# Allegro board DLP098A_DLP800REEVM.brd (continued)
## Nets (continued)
N16883884: R35.2 U11.3(D-)
N16883892: TP38.1 U11.4(THERM)
N16884055: R22.2 U9.13(1B1)
N16884056: R23.2 U9.12(1B2)
N16884057: R24.2 U9.11(2B1)
N16884058: R25.2 U9.10(2B2)
N16884072: R30.1 U10.3(A)
N16949503: C79.2 U13.3(CBOOT)
N16949505: C79.1 L7.1 U13.1(SW#1) U13.2(SW#2)
N16949620: C89.1 R44.2 R47.2 U13.9(FB)
N16949632: R45.2 U13.7(RT)
N16949636: C90.2 U13.4(VCC)
N16949644: R46.2 U13.6(SYNC)
N16949726: C91.2 U13.11(SS/TRK)
N16949871: R49.1 R51.1 U16.1(G)
N16949907: R50.1 U15.1(G) U16.3(D)
N16950963: U6.1(G) U14.4(Y)
N16971448: R55.1 R56.2 U17.4(FB)

Pads without a net: J500 B16 B17 B20 B21 B25 B28 B29 C30 C31 C34 D01 D04 D05 D29 D30 D31 D33 D34 D35 E18 E19 E33 E34 E36 E37 F01 F19 F20 F37 F38 H02 J18 J19 J21 J22 J36 J37 K16 K17 K19 K20 K22 K23 K37 K38; L5 3 4; L6 3 4; NOREF#4 1; NOREF#6 1; NOREF#8 1; NOREF#19 1; NOREF#20 1; NOREF#23 1; NOREF#28 1; NOREF#29 1; NOREF#30 1; NOREF#31 1; U4 1; U5 3; U7 51 52; U8 G1 H1 J1 J3 J4 K3 P3 R1 R3 R4 T1 U1 V3; U14 1

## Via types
v1: diameter 0.61, hole 0.305, TOP to BOTTOM, 1186 vias
v2: diameter 0.4, hole 0.2, TOP to BOTTOM, 20 vias

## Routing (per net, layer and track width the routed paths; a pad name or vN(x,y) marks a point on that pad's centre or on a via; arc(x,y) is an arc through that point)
GND: length 525.4
  TOP w0.191: 95.3,23.42 95.12,23.6 U7.1 ; U7.60 80.7,22.98 v1(80.42,22.71) ; U7.20 94.11,33.83 v1(93.9,34.03)
  TOP w0.254: U7.41 80.7,33.83 v1(80.91,34.05) ; L5.1 103.35,28.8 103.4,28.84 ; U7.14 v1(92.75,30.1) ; U7.55 81.76,26.1 82.16,25.7 v1(82.58,25.7) 82.58,26.49 81.96,27.1 U7.53 ; U11.5 v1(104.29,8.4) ; U7.46 v1(82.53,30.6) ; U7.7 v1(92.72,26.6) ; 104.33,28.81 103.45,27.93
  TOP w0.381: C37.1 15.67,51.38 v1(17.07,51.38) ; C37.1 14.66,50.94 ; C37.1 15.78,50.94 ; C37.1 15.22,51.62 ; v1(120.12,29.06) 119.23,29.95 R52.2 ; 10.72,7.95 C72.1 ; C72.1 11.28,7.26 ; C72.1 v1(12.22,7.95) ; 50.01,7.26 C33.1 ; C33.1 v1(50.95,7.95) ; C33.1 49.46,7.95 ; 57.08,7.95 C67.1 ; C67.1 v1(58.57,7.95) ; C67.1 57.63,7.26 ; 21.44,7.26 C41.1 ; C41.1 20.88,7.95 ; C41.1 v1(22.38,7.95) ; C53.1 v1(26.19,7.95) ; C53.1 24.69,7.95 ; C53.1 25.25,7.26 ; 17.07,7.95 C31.1 ; C31.1 v1(18.57,7.95) ; C31.1 17.63,7.26 ; C69.1 v1(62.38,7.95) ; C69.1 61.44,7.26 ; C69.1 60.89,7.95 ; C51.1 18.96,51.86 v1(18.15,51.86) ; C51.1 19.84,51.67 ; C51.1 19.28,50.98 ; C51.1 20.4,50.98 ; 59.54,7.26 C68.1 ; C68.1 v1(60.48,7.95) ; C68.1 58.98,7.95 ; 8.82,7.95 C55.1 ; C55.1 9.37,7.26 ; C55.1 v1(10.31,7.95) ; C36.1 21.49,51.67 ; C36.1 20.93,50.98 ; C36.1 21.62,50.98 v1(22.58,50.02) ; U4.3 109.87,42 v1(110,41.87) ; 43.36,50.81 C47.1 ; C47.1 44.48,50.81 ; C47.1 v1(43.92,51.88) ; U13.5 115.73,8.41 v1(115.29,7.98) ; C7.1 101.03,66.96 v1(100.83,66.76) ; 45.65,7.95 C63.1 ; C63.1 46.2,7.26 ; C63.1 v1(47.14,7.95) ; C84.2 v1(129.52,17.5) ; C46.1 13.62,51.8 ; C46.1 C52.1 ; C46.1 14.18,51.11 ; 18.98,7.95 C32.1 ; C32.1 v1(20.47,7.95) ; C32.1 19.53,7.26 ; C35.1 42.83,50.81 ; C35.1 41.71,50.81 ; C35.1 v1(42.27,51.88) ; v1(32.11,50.73) C57.1 30.31,50.73 30.26,50.77 ; R13.2 102.13,40.49 v1(101.7,40.06) ; C52.1 11.59,51.97 11.61,51.99 ; C52.1 10.74,51.11 v1(10.53,50.9) ; v1(30,7.95) C71.1 v1(28.09,7.95) C54.1 ; 36.68,7.26 C45.1 ; C45.1 36.12,7.95 ; C45.1 v1(37.62,7.95) ; 39.98,50.86 C50.1 ; C50.1 v1(40.54,51.93) ; C50.1 41.1,50.86 ; 12.63,7.95 C43.1 ; C43.1 v1(14.12,7.95) ; C43.1 13.18,7.26 ; 35.69,50.76 35.65,50.8 C65.1 v1(34.77,51.87) ; C24.1 v1(107.16,29.82) ; 41.2,7.95 C56.1 ; C56.1 41.76,7.26 ; C56.1 v1(42.7,7.95) ; C66.1 v1(56.67,7.95) ; C66.1 55.17,7.95 ; C66.1 55.73,7.26 ; C87.2 v1(128.75,16.99) ; 36.55,50.86 C58.1 ; C58.1 v1(37.11,51.93) ; C58.1 37.67,50.86 ; 53.27,7.95 C34.1 ; C34.1 v1(54.76,7.95) ; C34.1 53.82,7.26 ; C61.1 v1(49.05,7.95) ; C61.1 48.11,7.26 ; C61.1 47.55,7.95 ; C48.1 v1(38.64,51.93) ; C48.1 38.08,50.86 ; C48.1 39.2,50.86 ; v1(105,27.44) 105,27.55 104.62,27.93 L5.1 ; 95.3,23.42 v1(95.55,23.17) ; 26.6,7.95 C54.1 ; C54.1 27.15,7.26 ; 28.68,50.73 C39.1 ; C39.1 28.78,51.19 v1(28.52,51.19) ; C39.1 29.8,50.73 ; 23.34,7.26 C59.1 ; C59.1 22.79,7.95 ; C59.1 v1(24.28,7.95) ; v1(99.52,41.05) 99.47,40.99 D1.1 97.78,42.09 v1(97.24,42.63) ; R18.1 78.49,38.62 v1(78.18,38.93) ; v1(130.86,5.97) 130.86,5.97 C86.2 127.38,5.97 v1(126.85,5.44) ; 33.5,7.26 C70.1 ; C70.1 v1(34.44,7.95) ; C70.1 32.95,7.95 ; C29.1 v1(100.18,21.94) ; C22.1 v1(108.77,36.2) ; 44.3,7.26 C62.1 ; C62.1 v1(45.24,7.95) ; C62.1 43.74,7.95 ; v1(116.69,24.36) 117.59,25.26 U16.2 ; C77.1 v1(100.33,13.13) ; C21.1 v1(107.8,37.41) ; C1.1 v1(108.55,68.15) ; C30.1 v1(97.64,24.59) ; 39.22,7.26 C44.1 ; C44.1 v1(40.16,7.95) ; C44.1 38.66,7.95 ; v1(46.51,51.93) C42.1 45.68,50.86 45.65,50.83 ; C40.1 v1(52.86,7.95) ; C40.1 51.92,7.26 ; C40.1 51.36,7.95 ; D5.A v1(121.77,5.44) ; 15.72,7.26 C60.1 ; C60.1 15.17,7.95 ; C60.1 v1(16.66,7.95) ; v1(106.39,39.98) 107.16,40.74 R14.2 ; C8.1 v1(103.69,69.1) ; C64.1 v1(32.54,7.95) ; C64.1 31.6,7.26 ; C64.1 31.04,7.95 ; C49.1 v1(54.89,48.09) ; C23.1 v1(110.67,36.2) ; C2.1 v1(104.99,66.79) ; C38.1 v1(50.24,48.06) ; R19.2 v1(80.8,16.04)
  TOP w0.508: U8.Y9 v1(27.15,16.99) ; U8.B25 v1(48.74,42.39) ; U8.J24 v1(47.47,33.5) ; U8.X20 v1(42.39,18.26) ; U8.V24 v1(47.47,20.8) ; U8.F24 v1(47.47,37.31) ; U8.V4 v1(20.8,20.8) ; U8.H26 v1(50.01,34.77) ; v1(103.96,7.08) J3.4 v1(103.96,3.92) ; U8.L3 v1(19.53,30.96) ; U8.Y22 v1(44.93,16.99) ; U8.T2 v1(18.26,23.34) ; U8.V23 v1(46.2,20.8) ; U8.B7 v1(24.61,42.39) ; U8.D20 v1(42.39,39.85) ; U8.D9 v1(27.15,39.85) ; U8.X18 v1(39.85,18.26) ; U8.C24 v1(47.47,41.12) ; U8.E1 v1(16.99,38.58) ; U8.C9 v1(27.15,41.12) ; U8.L2 v1(18.26,30.96) ; U8.R24 v1(47.47,24.61) ; U8.E9 v1(27.15,38.58) ; U8.E2 v1(18.26,38.58) ; U8.L4 v1(20.8,30.96) ; U8.Z25 v1(48.74,15.72) ; U8.E16 v1(37.31,38.58) ; U8.M23 v1(46.2,28.42) ; U8.D2 v1(18.26,39.85) ; U8.Z20 v1(42.39,15.72) ; U8.X14 v1(34.77,18.26) ; U8.Z11 v1(29.69,15.72) ; U8.W1 v1(16.99,19.53) ; U8.H2 v1(18.26,34.77) ; U8.F4 v1(20.8,37.31) ; U8.W2 v1(18.26,19.53) ; U8.P2 v1(18.26,25.88) ; U8.X9 v1(27.15,18.26) ; U8.E26 v1(50.01,38.58) ; U8.B11 v1(29.69,42.39) ; U8.D18 v1(39.85,39.85) ; U8.E18 v1(39.85,38.58) ; U8.Y20 v1(42.39,16.99) ; U8.B4 v1(20.8,42.39) ; U8.D11 v1(29.69,39.85) ; U8.Y24 v1(47.47,16.99) ; U8.Z7 v1(24.61,15.72) ; U8.Y2 v1(18.26,16.99) ; U8.R23 v1(46.2,24.61) ; U8.X2 v1(18.26,18.26) ; U8.M1 v1(16.99,28.42) ; U8.H4 v1(20.8,34.77) ; U8.N2 v1(18.26,27.15) ; U8.D14 v1(34.77,39.85) ; U8.T26 v1(50.01,23.34) ; U8.D21 v1(43.66,39.85) ; U8.W25 v1(48.74,19.53) ; U8.Z22 v1(44.93,15.72) ; U8.B17 v1(38.58,42.39) ; U8.B20 v1(42.39,42.39) ; U8.W26 v1(50.01,19.53) ; U8.B22 v1(44.93,42.39) ; U8.E25 v1(48.74,38.58) ; U8.C22 v1(44.93,41.12) ; U8.W7 v1(24.61,19.53) ; U8.N3 v1(19.53,27.15) ; U8.C20 v1(42.39,41.12) ; U8.M2 v1(18.26,28.42) ; U8.T4 v1(20.8,23.34) ; U8.Z17 v1(38.58,15.72) ; U8.X5 v1(22.07,18.26) ; U8.X21 v1(43.66,18.26) ; U8.E17 v1(38.58,38.58) ; U8.B14 v1(34.77,42.39) ; U8.Z14 v1(34.77,15.72) ; U8.N4 v1(20.8,27.15) ; U8.J23 v1(46.2,33.5) ; U8.M24 v1(47.47,28.42) ; U8.C2 v1(18.26,41.12) ; U8.E7 v1(24.61,38.58) ; U8.F23 v1(46.2,37.31) ; U8.Z4 v1(20.8,15.72) ; U8.D1 v1(16.99,39.85) ; U8.W9 v1(27.15,19.53) ; U8.X1 v1(16.99,18.26) ; U8.D5 v1(22.07,39.85) ; U8.T25 v1(48.74,23.34) ; U8.X11 v1(29.69,18.26) ; U8.K2 v1(18.26,32.23) ; U8.H25 v1(48.74,34.77)
  02_GND1 w0.381: TP12.1 117.93,50.95 ; TP12.1 116.49,49.5 ; TP12.1 117.93,48.06 ; TP12.1 119.38,49.5
  04_GND2 w0.381: 116.49,49.5 TP12.1 ; TP12.1 117.93,48.06 ; TP12.1 117.93,50.95 ; TP12.1 119.38,49.5
  09_GND3 w0.381: TP12.1 119.38,49.5 ; TP12.1 117.93,50.95 ; TP12.1 116.49,49.5 ; TP12.1 117.93,48.06
  11_GND4 w0.381: TP12.1 117.93,50.95 ; TP12.1 119.38,49.5 ; TP12.1 116.49,49.5 ; TP12.1 117.93,48.06
  BOTTOM w0.254: U9.15 23.8,53.22 24.3,52.72 ; v1(114.4,37.83) 114.61,37.62 U1.5 ; 24.3,52.72 U9.17 ; 24.3,52.72 U9.14 22.6,52.72 22.29,53.03 22.29,53.44 v1(22.3,53.45) ; v1(25.8,48.92) U9.8 25.8,51.22 U9.17 ; U9.17 24.3,51.22 U9.9 v1(24.3,48.94) ; v1(90.06,36.52) 89.54,36 C28.1 ; C73.1 v1(19.84,55.78)
  BOTTOM w0.305: U10.2 v1(14.4,52.23)
  BOTTOM w0.381: J500.B33 v1(94.91,84.6) ; J500.B13 v1(68.24,84.6) ; J500.C24 v1(83.48,83.33) ; J500.J14 v1(69.51,74.44) ; C80.2 124.51,15.85 ; C80.2 123.04,14.88 ; C80.2 123.04,16.81 ; C80.2 121.57,15.85 ; J500.C21 v1(79.67,83.33) ; v1(96.81,66.64) 97.06,66.9 C3.1 ; J500.G01 v1(53,76.98) ; J500.K36 v1(98.72,73.17) ; J500.B31 v1(92.37,84.6) ; J500.G35 v1(97.45,76.98) ; C74.1 v1(31.14,55.41) ; R26.1 32.15,52.99 v1(32.83,52.32) 32.23,51.72 R27.1 ; J500.C36 v1(98.72,83.33) ; J500.B39 v1(102.53,84.6) ; J500.G20 v1(77.13,76.98) ; J500.C33 v1(94.91,83.33) ; J500.D28 v1(88.56,82.06) ; R44.1 C89.2 ; J500.B03 v1(55.54,84.6) ; J500.E04 v1(56.81,80.79) ; J500.A09 v1(63.16,85.87) ; J500.E35 v1(97.45,80.79) ; v1(92.75,30.1) 93.01,29.84 C17.1 ; J500.C12 v1(66.97,83.33) ; J500.E40 v1(103.8,80.79) ; C82.2 119.23,16.81 ; C82.2 117.76,15.85 ; C82.2 120.7,15.85 ; C82.2 119.23,14.88 ; J500.A04 v1(56.81,85.87) ; J500.A16 v1(72.05,85.87) ; J500.E32 v1(93.64,80.79) ; J500.G11 v1(65.7,76.98) ; v1(100.18,15.72) C93.1 v1(102.59,17.5) ; v1(127.14,42.58) 127.52,42.58 128.1,43.16 U14.3 ; v1(80.91,34.05) 80.98,34.11 C27.1 ; J500.A17 v1(73.32,85.87) ; J500.G05 v1(58.08,76.98) ; J500.H15 v1(70.78,75.71) ; J500.H21 v1(79.67,75.71) ; J500.H06 v1(59.35,75.71) ; J500.A24 v1(83.48,85.87) ; v1(122.07,37.37) 121.82,37.12 R9.1 ; C9.1 v1(117.4,40.95) ; C19.1 82.25,30.33 v1(82.53,30.6) ; C76.1 v1(11.99,55.37) ; J500.F12 v1(66.97,78.25) ; J500.B18 v1(74.59,84.6) ; v1(103.61,26.03) 104.39,25.25 R56.1 ; J500.G32 v1(93.64,76.98) ; C10.1 108.94,32.36 v1(109.86,33.27) ; J500.G04 v1(56.81,76.98) ; J500.F30 v1(91.1,78.25) ; J500.D10 v1(64.43,82.06) ; J500.B19 v1(75.86,84.6) ; J500.K30 v1(91.1,73.17) ; J500.E01 v1(53,80.79) ; J500.C40 v1(103.8,83.33) ; J500.C28 v1(88.56,83.33) ; U2.3 113.85,28.99 v1(113.64,29.19) ; J500.D06 v1(59.35,82.06) ; J500.A33 v1(94.91,85.87) ; J500.E23 v1(82.21,80.79) ; C94.1 99.42,24.77 v1(98.1,23.44) ; R15.2 v1(125.66,37.59) ; J500.G14 v1(69.51,76.98) ; J500.K06 v1(59.35,73.17) ; J500.G23 v1(82.21,76.98) ; J500.D22 v1(80.94,82.06) ; J500.C20 v1(77.13,83.33) ; J500.A27 v1(87.29,85.87) ; J500.A35 v1(97.45,85.87) ; J500.J32 v1(93.64,74.44) ; J500.B14 v1(69.51,84.6) ; J500.F15 v1(70.78,78.25) ; C4.1 v1(99.73,69.36) ; J500.G38 v1(101.26,76.98) ; J500.A05 v1(58.08,85.87) ; v1(93.45,22.33) 93.09,21.98 C26.1 ; J500.A08 v1(61.89,85.87) ; J500.B35 v1(97.45,84.6) ; J500.K02 v1(54.27,73.17) ; J500.C01 v1(53,83.33) ; J500.C29 v1(89.83,83.33) ; J500.F27 v1(87.29,78.25) ; R17.1 81.33,32.06 v1(82.15,32.88) ; C5.1 v1(95.77,69.31) ; J500.F03 v1(55.54,78.25) ; J500.K15 v1(70.78,73.17) ; J500.G17 v1(73.32,76.98) ; J500.A12 v1(68.24,85.87) J500.A13 ; J500.J08 v1(61.89,74.44) ; J500.J01 v1(53,74.44) ; v1(116.49,38.12) U1.7 ; J500.A11 v1(65.7,85.87) ; J500.D02 v1(54.27,82.06) ; J500.D16 v1(72.05,82.06) ; J500.K39 v1(102.53,73.17) ; J500.E05 v1(58.08,80.79) ; J500.A28 v1(88.56,85.87) ; J500.G08 v1(61.89,76.98) ; J500.D37 v1(99.99,82.06) ; C12.1 109.45,25.02 v1(109.5,24.97) ; J500.D25 v1(84.75,82.06) ; J500.J04 v1(56.81,74.44) ; J500.J38 v1(101.26,74.44) ; J500.B09 v1(63.16,84.6) ; U17.3 v1(105.89,18.14) ; C16.1 98.25,39.78 v1(99.52,41.05) ; J500.H03 v1(55.54,75.71) ; C20.1 v1(76.68,34.09) ; J500.K09 v1(63.16,73.17) ; J500.E29 v1(89.83,80.79) ; J500.H27 v1(87.29,75.71) ; J500.K24 v1(83.48,73.17) ; J500.J26 v1(86.02,74.44) ; J500.H30 v1(91.1,75.71) ; J500.J35 v1(97.45,74.44) ; U6.2 123.36,42.91 v1(123.37,42.9) ; J500.K12 v1(66.97,73.17) ; J500.E26 v1(86.02,80.79) ; C6.1 v1(92.26,67.43) ; J500.J05 v1(58.08,74.44) ; J500.A19 v1(75.86,85.87) ; J500.A36 v1(98.72,85.87) ; J500.H09 v1(63.16,75.71) ; J500.A39 v1(102.53,85.87) ; C15.1 82.03,28.55 v1(82.91,28.55) ; J500.B26 v1(86.02,84.6) ; J500.C38 v1(101.26,83.33) ; C75.1 14.73,52.23 v1(14.4,52.23) ; J500.A29 v1(89.83,85.87) ; v1(79.35,22.84) 79.35,24.03 79.73,24.42 C18.1 ; C11.1 v1(121.9,40.24) ; v1(105.89,11.91) U17.6 102.77,13.87 v1(102.74,13.84) ; R21.1 v1(9.83,53.37) ; J500.F36 v1(98.72,78.25) ; J500.C07 v1(60.62,83.33) ; J500.B05 v1(58.08,84.6) ; J500.E17 v1(73.32,80.79) ; C13.1 v1(83.67,16.11) ; J500.C05 v1(58.08,83.33) ; J500.F02 v1(54.27,78.25) ; J500.E20 v1(77.13,80.79) ; J500.A37 v1(99.99,85.87) ; J500.J17 v1(73.32,74.44) ; J500.J11 v1(65.7,74.44) ; J500.E14 v1(69.51,80.79) ; J500.C32 v1(93.64,83.33) ; J500.C17 v1(73.32,83.33) ; J500.A03 v1(55.54,85.87) ; J500.H33 v1(94.91,75.71) ; J500.B15 v1(70.78,84.6) ; J500.D19 v1(75.86,82.06) ; J500.K33 v1(94.91,73.17) ; J500.J29 v1(89.83,74.44) ; J500.C25 v1(84.75,83.33) ; J500.K21 v1(79.67,73.17) ; J500.B23 v1(82.21,84.6) ; J500.C08 v1(61.89,83.33) ; J500.A23 v1(82.21,85.87) ; J500.C13 v1(68.24,83.33) ; v1(130.97,8.23) C85.2 127.25,8.23 v1(126.71,7.68) ; v1(32.11,50.73) 32.11,50.67 31.73,50.29 30.95,50.29 R28.1 R29.1 ; J500.J23 v1(82.21,74.44) ; J500.B10 v1(64.43,84.6) ; J500.B11 v1(65.7,84.6) ; J500.H24 v1(83.48,75.71) ; J500.F18 v1(74.59,78.25) ; J500.C16 v1(72.05,83.33) ; J500.A15 v1(70.78,85.87) ; J500.F09 v1(63.16,78.25) ; J500.B02 v1(54.27,84.6) ; J500.B30 v1(91.1,84.6) ; J500.B37 v1(99.99,84.6) ; J500.B06 v1(59.35,84.6) ; U5.2 v1(128.45,41.48) ; J500.B38 v1(101.26,84.6) ; J500.D03 v1(55.54,82.06) ; J500.B22 v1(80.94,84.6) ; J500.A25 v1(84.75,85.87) ; J500.E08 v1(61.89,80.79) ; J500.A21 v1(79.67,85.87) ; C25.1 v1(87.35,15.86) ; J500.F24 v1(83.48,78.25) ; J500.H36 v1(98.72,75.71) ; J500.G40 v1(103.8,76.98) ; J500.A31 v1(92.37,85.87) ; J500.A01 v1(53,85.87) ; J500.A40 v1(103.8,85.87) ; J500.B27 v1(87.29,84.6) ; J500.E38 v1(101.26,80.79) ; J500.H39 v1(102.53,75.71) ; J500.B34 v1(96.18,84.6) ; J500.C04 v1(56.81,83.33) ; J500.A32 v1(93.64,85.87) ; C14.1 v1(89.38,15.7) ; J500.A20 v1(77.13,85.87) ; J500.K27 v1(87.29,73.17) ; J500.H12 v1(66.97,75.71) ; R31.1 v1(10.39,48.59) ; J500.D13 v1(68.24,82.06) ; J500.G29 v1(89.83,76.98) ; J500.A07 v1(60.62,85.87) ; J500.H18 v1(74.59,75.71) ; J500.C03 v1(55.54,83.33) ; J500.F06 v1(59.35,78.25) ; J500.F39 v1(102.53,78.25) ; J500.C09 v1(63.16,83.33) ; J500.D39 v1(102.53,82.06) ; J500.B07 v1(60.62,84.6) ; J500.D07 v1(60.62,82.06) ; J500.F21 v1(79.67,78.25) ; J500.K03 v1(55.54,73.17) ; J500.E11 v1(65.7,80.79) ; J500.G26 v1(86.02,76.98) ; J500.K18 v1(74.59,73.17) ; J500.F33 v1(94.91,78.25) ; J500.J40 v1(103.8,74.44) ; J500.J20 v1(77.13,74.44)
  BOTTOM w1.016: v1(123.67,17.63) 125.2,17.63 125.83,16.99 125.83,12.04 123.04,9.25 C89.2
  vias: v1(0.99,49.25) v1(0.99,46.71) v1(0.99,44.17) v1(0.99,41.63) v1(0.99,39.09) v1(0.99,36.55) v1(0.99,34.01) v1(0.99,31.47) v1(0.99,28.93) v1(0.99,26.39) v1(0.99,23.85) v1(0.99,21.31) v1(0.99,18.77) v1(0.99,16.23) v1(0.99,13.69) v1(0.99,11.15) v1(0.99,8.61) v1(0.99,6.07) v1(0.99,3.53) v1(1.63,0.99) v1(2.55,51.15) v1(4.17,0.99) v1(4.34,52.94) v1(6.14,54.74) v1(6.71,0.99) v1(7.94,56.53) v1(9.25,0.99) v1(9.73,58.33) v1(11.53,60.13) v1(11.79,0.99) v1(13.32,61.92) v1(14.33,0.99) v1(15.12,63.72) v1(16.92,65.51) v1(16.87,0.99) v1(18.71,67.31) v1(19.41,0.99) v1(20.55,69.01) v1(21.95,0.99) v1(22.45,69.01) v1(24.36,69.01) v1(24.49,0.99) v1(26.26,69.01) v1(27.03,0.99) v1(28.17,69.01) v1(29.57,0.99) v1(30.07,69.01) v1(31.98,69.01) v1(32.11,0.99) v1(33.88,69.01) v1(34.65,0.99) v1(35.79,69.01) v1(37.19,0.99) v1(37.69,69.01) v1(39.6,69.01) v1(39.73,0.99) v1(41.5,69.01) v1(42.27,0.99) v1(43.41,69.01) v1(44.81,0.99) v1(45.31,69.01) v1(47.22,69.01) v1(47.35,0.99) v1(48.29,85.94) v1(48.29,83.4) v1(48.29,80.86) v1(48.29,78.32) v1(48.29,75.78) v1(48.29,73.24) v1(48.29,70.7) v1(49.47,87.42) v1(49.89,0.99) v1(52.01,87.42) v1(52.43,0.99) v1(54.55,87.42) v1(54.97,0.99) v1(57.09,87.42) v1(57.51,0.99) v1(59.63,87.42) v1(60.05,0.99) v1(62.17,87.42) v1(62.59,0.99) v1(64.71,87.42) v1(65.13,0.99) v1(67.25,87.42) v1(67.67,0.99) v1(69.79,87.42) v1(70.21,0.99) v1(72.33,87.42) v1(72.75,0.99) v1(74.87,87.42) v1(75.29,0.99) v1(77.41,87.42) v1(77.83,0.99) v1(79.95,87.42) v1(80.37,0.99) v1(82.49,87.42) v1(82.91,0.99) v1(85.03,87.42) v1(85.45,0.99) v1(87.57,87.42) v1(87.99,0.99) v1(90.11,87.42) v1(90.53,0.99) v1(92.65,87.42) v1(93.07,0.99) v1(93.83,18.14) v1(95.19,87.42) v1(95.61,0.99) v1(97.73,87.42) v1(99.88,38.56) v1(100.27,87.42) v1(100.69,0.99) v1(102.81,87.42) v1(102.79,28.81) v1(103.23,0.99) v1(105.06,28.42) v1(105.35,87.42) v1(107.89,87.42) v1(108.31,0.99) v1(108.51,85.95) v1(108.51,83.41) v1(108.51,80.87) v1(108.51,78.33) v1(108.51,75.79) v1(108.51,73.25) v1(108.51,70.71) v1(109.79,69.01) v1(110.85,0.99) v1(112.33,69.01) v1(113.39,0.99) v1(114.87,69.01) v1(115.93,0.99) v1(116.49,37.12) v1(117.41,69.01) v1(118.47,0.99) v1(119.95,69.01) v1(121.01,0.99) v1(121.13,18.9) v1(121.13,17.63) v1(121.52,24.67) v1(121.64,33) v1(121.64,30.45) v1(121.64,28.94) v1(121.64,27.03) v1(122.4,18.9) v1(122.4,17.63) v1(122.49,69.01) v1(123.55,0.99) v1(123.67,18.9) v1(125.03,69.01) v1(126.09,0.99) v1(127.57,69.01) v1(128.63,0.99) v1(129.52,21.56) v1(130.11,69.01) v1(130.28,35.92) v1(130.28,33.89) v1(130.28,32.11) v1(130.28,30.08) v1(130.28,27.92) v1(130.79,16.99) v1(131.17,0.99) v1(132.02,68.72) v1(132.02,66.18) v1(132.02,63.64) v1(132.02,61.1) v1(132.02,58.56) v1(132.02,56.02) v1(132.02,53.48) v1(132.02,50.94) v1(132.02,48.4) v1(132.02,45.86) v1(132.02,43.32) v1(132.02,40.78) v1(132.02,38.24) v1(132.02,35.7) v1(132.02,33.16) v1(132.02,30.62) v1(132.02,28.08) v1(132.02,25.54) v1(132.02,23) v1(132.02,20.46) v1(132.02,17.92) v1(132.02,15.38) v1(132.02,12.84) v1(132.02,10.3) v1(132.02,7.76) v1(132.02,5.22) v1(132.02,2.68)
P1V8: length 129.9
  TOP w0.381: C65.2 34.77,48.37 v1(34.49,48.09) ; C58.2 v1(37.11,48.21) ; C51.2 v1(19.84,48.17) ; C48.2 v1(38.64,48.21) ; C47.2 v1(43.92,48.16) ; C52.2 v1(11.59,48.29) ; C57.2 v1(31.02,47.91) ; C46.2 v1(13.62,48.29) ; C50.2 v1(40.54,48.21) ; v1(53.32,48.09) C49.2
  TOP w0.508: C60.2 15.72,10.21 ; C60.2 15.17,9.53 ; C60.2 v1(16.66,9.53) ; 36.55,49.28 C58.2 37.67,49.28 ; 24.69,9.53 C53.2 ; C53.2 25.25,10.21 ; C53.2 v1(26.19,9.53) ; 58.98,9.53 C68.2 ; C68.2 59.54,10.21 ; C68.2 v1(60.48,9.53) ; U8.Z1 v1(16.99,15.72) ; U8.M3 v1(19.53,28.42) ; 26.6,9.53 C54.2 ; C54.2 27.15,10.21 ; C54.2 v1(28.09,9.53) ; U8.D22 v1(44.93,39.85) ; C70.2 v1(34.44,9.53) ; C70.2 33.5,10.21 ; C70.2 32.95,9.53 ; 39.68,49.26 39.71,49.28 C50.2 ; U8.F2 v1(18.26,37.31) ; U8.W19 v1(41.12,19.53) ; C71.2 v1(30,9.53) ; C71.2 28.5,9.53 ; C71.2 29.06,10.21 ; 39.2,49.28 C48.2 38.08,49.28 ; U8.Y1 v1(16.99,16.99) ; C61.2 48.11,10.21 ; C61.2 v1(49.05,9.53) ; C61.2 47.55,9.53 ; 57.08,9.53 C67.2 ; C67.2 57.63,10.21 ; C67.2 v1(58.57,9.53) ; U8.L25 v1(48.74,30.96) ; v1(56.67,9.53) C66.2 55.73,9.99 56,10.26 ; C44.2 39.22,10.21 ; C44.2 v1(40.16,9.53) ; C44.2 38.66,9.53 ; C56.2 41.76,10.21 ; C56.2 v1(42.7,9.53) ; C56.2 41.2,9.53 ; U8.C1 v1(16.99,41.12) ; U8.X22 v1(44.93,18.26) ; U8.X19 v1(41.12,18.26) ; C62.2 v1(45.24,9.53) ; C62.2 44.3,10.21 ; C62.2 43.74,9.53 ; v1(24.28,9.53) C59.2 23.34,10.02 23.58,10.26 ; 60.89,9.53 C69.2 ; C69.2 61.44,10.21 ; C69.2 v1(62.38,9.53) ; U8.A7 v1(24.61,43.66) ; U8.A11 v1(29.69,43.66) ; 31.04,9.53 C64.2 ; C64.2 v1(32.54,9.53) ; C64.2 31.6,10.21 ; U8.W22 v1(44.93,19.53) ; C72.2 11.28,10.21 ; C72.2 v1(12.22,9.53) ; C72.2 10.72,9.53 ; U8.A5 v1(22.07,43.66) ; U8.D12 v1(30.96,39.85) ; U8.AA23 v1(46.2,14.45) ; U8.A8 v1(25.88,43.66) ; U8.A16 v1(37.31,43.66) ; U8.W20 v1(42.39,19.53) ; U8.AA16 v1(37.31,14.45) ; U8.A22 v1(44.93,43.66) ; U8.A17 v1(38.58,43.66) ; U8.AA8 v1(25.88,14.45) ; U8.A18 v1(39.85,43.66) ; 32,49.11 31.95,49.16 C57.2 ; 35.33,49.23 C65.2 34.22,49.23 ; C43.2 v1(14.12,9.53) ; C43.2 13.18,10.21 ; C43.2 12.63,9.53 ; U8.AA6 v1(23.34,14.45) ; U8.A21 v1(43.66,43.66) ; U8.J2 v1(18.26,33.5) ; U8.AA11 v1(29.69,14.45) ; U8.N1 v1(16.99,27.15) ; U8.D19 v1(41.12,39.85) ; U8.E22 v1(44.93,38.58) ; U8.N25 v1(48.74,27.15) ; U8.L1 v1(16.99,30.96) ; U8.A23 v1(46.2,43.66) ; U8.E8 v1(25.88,38.58) ; U8.F1 v1(16.99,37.31) ; C55.2 v1(10.31,9.53) ; C55.2 8.82,9.53 ; C55.2 9.37,10.21 ; U8.AA21 v1(43.66,14.45) ; 36.12,9.53 C45.2 ; C45.2 36.68,10.21 ; C45.2 v1(37.62,9.53) ; U8.M25 v1(48.74,28.42) ; U8.W21 v1(43.66,19.53) ; C46.2 12.55,49.54 12.48,49.46 12.4,49.54 C52.2 ; U8.V2 v1(18.26,20.8) ; U8.X12 v1(30.96,18.26) ; U8.K1 v1(16.99,32.23) ; U8.AA17 v1(38.58,14.45) ; U8.R2 v1(18.26,24.61) ; U8.M4 v1(20.8,28.42) ; U8.AA22 v1(44.93,14.45) ; U8.AA2 v1(18.26,14.45) ; C63.2 v1(47.14,9.53) ; C63.2 45.65,9.53 ; C63.2 46.2,10.21 ; U8.AA7 v1(24.61,14.45) ; U8.V1 v1(16.99,20.8) ; U8.A6 v1(23.34,43.66) ; U8.D10 v1(28.42,39.85) ; U8.E21 v1(43.66,38.58) ; U8.AA5 v1(22.07,14.45) ; U8.Z2 v1(18.26,15.72) ; U8.X10 v1(28.42,18.26) ; U8.E20 v1(42.39,38.58) ; U8.E19 v1(41.12,38.58) ; U8.W8 v1(25.88,19.53) ; U8.AA18 v1(39.85,14.45) ; U8.P1 v1(16.99,25.88) ; U8.B2 v1(18.26,42.39)
  06_PWR1 w0.508: 6.73,49.69 TP5.1 ; TP5.1 7.52,50.48 ; TP5.1 7.52,48.9 ; TP5.1 8.31,49.69
  BOTTOM w0.254: v1(23.33,54.36) 23.73,53.95 U9.16
  BOTTOM w0.381: U10.6 11.37,53.4
  BOTTOM w0.508: C73.2 22.95,54.74 v1(23.33,54.36) ; v1(10.42,55.41) C76.2 10.42,54.35 11.37,53.4
  BOTTOM w0.635: C10.2 112.01,30.69 v1(113.67,30.69) 113.67,30.69 U2.4
P3V3: length 56.5
  TOP w0.381: U4.5 113.24,44.06 R11.1
  TOP w0.508: R2.1 v1(56.17,66.36) ; R4.1 v1(52.34,66.36) ; L1.1 C1.2 107.66,65.37 v1(107.58,65.3) ; L1.1 105.72,66.58 ; L1.1 106.28,65.32 v1(106.26,65.3) ; R3.1 v1(84.14,66.36) ; U3.3 106.77,45.3 v1(108.03,44.04) ; R11.1 114.19,44.2 v1(114.65,43.74) ; R11.1 113.38,44.88 ; R11.1 112.82,44.2 ; R5.1 v1(90.57,66.36) ; C8.2 104.25,66.58 ; C8.2 L4.1 ; C8.2 103.69,65.37 v1(103.62,65.3) ; v1(102.3,65.3) 102.32,65.32 L4.1 ; v1(102.71,7.08) J3.3 v1(102.71,3.92) ; v1(116.18,2.64) 116.41,2.87 R42.2 ; U11.1 98.64,11.8 C77.2 v1(98.76,13.03) ; R1.1 v1(62.51,66.36) ; 101.76,66.58 L4.1 ; 112.19,44.75 112.07,44.63 U4.5 ; R32.1 v1(108.43,10.64) ; R33.1 v1(108.43,9.37)
  BOTTOM w0.254: 26.77,53.81 26.63,53.95 U9.1 ; 26.77,53.81 26.77,53.81 ; 26.77,53.81 U9.2 ; 96.42,65.99 95.83,66.58 C5.2 ; U14.5 v1(129.4,47.46) ; U10.1 15.64,52.88 C75.2 ; 27.57,52.72 U9.3
  BOTTOM w0.381: C75.2 15.65,54.01 15.85,54.21
  BOTTOM w0.508: v1(113.67,27.29) 112.38,27.29 C12.2 ; C74.2 28.49,55.97 ; C74.2 27.8,55.41 ; C74.2 28.49,54.85 ; R7.1 121.85,35.72 v1(122.1,35.97) ; v1(113.95,22.56) R6.2 ; 25.8,54.55 U9.1 25.48,53.95 ; 97.8,66.58 L2.1 ; L2.1 98.92,66.58 ; L2.1 98.36,65.89 ; 16.21,52.89 C75.2 15.09,52.89 ; 99.17,66.58 C4.2 99.73,65.89 ; 95.77,65.89 C5.2 95.21,66.58 ; L3.1 94.96,66.58 ; L3.1 93.84,66.58 ; L3.1 94.4,65.89
  BOTTOM w0.635: U2.2 113.67,27.29 v1(113.67,27.29)
  vias: v1(115.34,44.6) v1(115.81,43.74)
P12V: length 25.9
  TOP w0.254: U7.48 v1(82.43,29.6) ; U7.50 81.8,28.6 82.47,27.93 v1(82.47,27.53) ; U7.11 v1(95.74,28.6)
  TOP w0.508: U15.2 124.67,34.88 v1(124.77,34.98) ; v1(121.64,25.76) 122.43,25.76 R50.2 ; R53.1 v1(128.91,35.05)
  BOTTOM w0.254: v1(114.66,39.1) 114.66,38.87 115.26,38.27 U1.6
  BOTTOM w0.508: C17.2 95.29,28.27 95.62,28.6 v1(95.74,28.6) ; C18.2 82.15,27.21 v1(82.47,27.53) ; U5.4 129.4,36.61 v1(129.14,36.35) ; J500.C37 v1(99.99,83.33) ; U17.1 v1(103.35,21.74) ; J500.C35 v1(97.45,83.33) ; v1(114.66,39.1) 115.34,39.78 C9.2 ; v1(101.5,21.95) 101.5,21.18 100.61,20.29 100.18,20.29 ; U5.5 v1(127.5,36.31)
  vias: v1(130.66,12.55) v1(130.66,11.28) v1(130.66,10.01)
VCC2: length 49.5
  TOP w0.381: 18.98,9.53 C32.2 19.53,10.21 ; C37.2 v1(15.22,48.18) ; C31.2 17.63,10.1 17.88,10.35 ; 51.92,10.21 C40.2 51.36,9.53 ; 20.88,9.53 C41.2 21.44,10.21 ; C35.2 v1(42.27,48.16) ; C36.2 v1(21.49,48.17) ; 53.82,10.21 C34.2 53.27,9.53 ; C39.2 v1(29.24,47.91) ; v1(48.67,48.06) C38.2 47.83,49.33 47.8,49.36 ; v1(46.51,48.21) C42.2 47.31,49.28 47.36,49.33 ; C33.2 50.01,10.05 50.26,10.29
  TOP w0.508: U8.A25 v1(48.74,43.66) ; C41.2 v1(22.38,9.53) ; U8.N26 v1(50.01,27.15) ; U8.A3 v1(19.53,43.66) ; U8.AA25 v1(48.74,14.45) ; U8.AA4 v1(20.8,14.45) ; U8.A4 v1(20.8,43.66) ; C32.2 v1(20.47,9.53) ; C40.2 v1(52.86,9.53) ; U8.Z26 v1(50.01,15.72) ; U8.L26 v1(50.01,30.96) ; U8.B26 v1(50.01,42.39) ; C33.2 v1(50.95,9.53) ; C34.2 v1(54.76,9.53) ; C31.2 v1(18.57,9.53) ; U8.M26 v1(50.01,28.42) ; U8.AA3 v1(19.53,14.45)
  07_PWR2 w0.381: TP4.1 120.02,42.39 ; TP4.1 118.44,42.39 ; TP4.1 119.23,43.18 ; TP4.1 119.23,41.61
  BOTTOM w0.254: U1.1 117.52,38.27 v1(118.09,38.84)
  BOTTOM w0.381: v1(101.6,28.02) 102.21,27.41 C94.2 103.15,24.31 v1(104.47,24.31) R55.2 104.47,22.2 v1(104.62,22.05) U17.2 ; C11.2 118.6,39.63 118.6,39.35 v1(118.09,38.84) ; R10.1 v1(121.13,43.66)
  BOTTOM w0.508: R8.2 v1(122.07,38.64)
VCC2_EN: length 43.8
  TOP w0.381: U4.4 113.24,42.76 R11.2
  TOP w0.508: 112.82,42.62 R11.2 ; R11.2 113.94,42.62 ; R11.2 113.38,41.5 v1(113.31,41.43) ; 113.13,38.62 TP6.1 112.35,37.83 ; 112.13,42.03 112.07,42.1 U4.4
  BOTTOM w0.254: U1.4 113.99,36.97 113.74,37.22
  BOTTOM w0.635: 111.94,34.45 111.94,35.13 112.82,36.02 112.82,37.52 TP6.1 ; 111.94,34.45 114,32.39 U2.5 ; 111.94,34.45 111.84,34.35 108.01,34.35 103.99,30.33 103.99,27.15 104.82,26.33 106.8,26.33 108.43,24.7 U17.5 ; v1(113.31,41.43) 113.13,41.25 TP6.1 ; 113.74,37.22 TP6.1
3P3VAUX: length 0.9
  BOTTOM w0.508: J500.D32 v1(93.64,82.06)
DAD_ADDR_0: length 96.4
  TOP w0.191: v1(69.51,85.87) 70.14,85.24 70.14,61.97 71.58,60.53 78.1,60.53 78.72,59.91 78.72,57.29 78.14,56.71 66.99,56.71 66.33,56.06 66.33,54.44 66.92,53.86 78.72,53.86 87.99,44.59 92.48,44.59 94.18,42.88 94.18,38.78 93.83,38.43 93.83,34.93 92.69,33.79 92.69,32.98 93.06,32.6 U7.19
  BOTTOM w0.191: J500.A14 v1(69.51,85.87)
DAD_ADDR_1: length 96.3
  TOP w0.191: v1(74.59,85.87) 75.22,85.24 75.22,74.81 71.91,71.5 71.91,62.33 72.79,61.45 78.9,61.45 79.99,60.36 79.99,56.82 79.1,55.93 68.01,55.93 67.65,55.56 67.65,55.03 68,54.67 79.61,54.67 88.75,45.53 92.34,45.53 94.64,43.23 94.64,38.39 94.54,38.29 94.54,34.48 95.28,33.74 95.28,32.29 95.09,32.1 U7.18
  BOTTOM w0.191: J500.A18 v1(74.59,85.87)
DAD_ADDR_2: length 96.3
  TOP w0.191: U7.17 95.18,31.6 95.66,32.09 95.66,33.99 95.14,34.52 95.14,40.17 95.14,40.59 95.14,43.66 92.49,46.31 89.13,46.31 81.58,53.86 81.58,61.61 80.71,62.48 73.61,62.48 73.25,62.83 73.25,63.72 73.67,64.14 81.72,64.14 82.03,64.44 82.03,65 81.62,65.41 73.69,65.41 73.31,65.78 73.31,66.75 73.77,67.21 80.96,67.21 81.58,67.82 81.58,85.24 v1(80.94,85.87)
  BOTTOM w0.191: J500.A22 v1(80.94,85.87)
DAD_ADDR_3: length 96.3
  TOP w0.191: U7.16 95.18,31.1 96.04,31.96 96.04,34.29 95.61,34.72 95.61,44.17 92.34,47.43 89.46,47.43 87.45,49.44 87.45,68.45 87.15,68.75 86.56,68.75 86.29,68.47 86.29,53.35 85.97,53.03 85.44,53.03 85.08,53.39 85.08,70.9 86.65,72.47 86.65,85.24 v1(86.02,85.87)
  BOTTOM w0.191: J500.A26 v1(86.02,85.87)
DAD_IRQZ: length 96.4
  TOP w0.191: v1(61.89,84.6) 62.52,83.97 62.52,69.06 R1.2 67.17,69.04 67.99,68.22 67.99,63.78 67.31,63.1 62.67,63.1 62.23,62.66 62.23,61.57 62.67,61.14 66.98,61.14 67.42,60.69 67.42,59.01 66.9,58.49 59.59,58.49 58.31,57.21 58.31,54.36 60.44,52.22 75.7,52.22 78.03,49.89 78.03,41.12 80.05,39.1 80.05,36.54 78.83,35.31 78.83,32.91 79.63,32.1 U7.43
  BOTTOM w0.191: J500.B08 v1(61.89,84.6)
DAD_MODE_0: length 92.9
  TOP w0.191: v1(59.97,62.06) 59.98,62.08 59.98,85.24 v1(59.35,85.87) ; U7.3 v1(92.76,24.6)
  03_SIG1 w0.133: v1(92.76,24.6) 94.19,26.04 94.19,28.55 96.04,30.4 96.04,44.99 v1(95.77,45.27)
  BOTTOM w0.191: v1(95.77,45.27) 95.77,46.81 94.69,47.89 90.21,47.89 89.31,46.99 75.04,46.99 v1(59.97,62.06) ; J500.A06 v1(59.35,85.87)
DAD_MODE_1: length 95.8
  TOP w0.191: v1(95.61,24.29) 95.42,24.1 U7.2 ; v1(90.47,43.64) 87.53,43.64 78.15,53.02 66.3,53.02 65.41,53.91 65.41,56.59 66.29,57.47 67,57.47 69.23,59.69 69.23,68.32 65.06,72.49 65.06,85.24 v1(64.43,85.87)
  03_SIG1 w0.133: v1(90.47,43.64) 93.06,43.64 94.38,42.33 94.38,35.48 91.91,33.02 91.91,23.91 92.27,23.55 94.87,23.55 v1(95.61,24.29)
  BOTTOM w0.191: J500.A10 v1(64.43,85.87)
DAD_OEZ: length 92.9
  TOP w0.191: v1(56.81,84.6) 56.17,83.97 56.17,69.05 R2.2 57.17,68.04 v1(57.17,62.06) ; v1(95.43,26.42) 95.12,26.1 U7.6
  03_SIG1 w0.133: v1(95.43,26.42) 95.69,26.42 97.82,28.54 97.82,43.16 v1(96.8,44.17)
  BOTTOM w0.191: v1(96.8,44.17) 96.8,43.81 96.28,43.29 94.6,43.29 91.82,46.08 74.35,46.08 58.36,62.06 v1(57.17,62.06) ; J500.B04 v1(56.81,84.6)
DAD_SEL_0: length 95.7
  TOP w0.191: v1(91.1,85.87) 89.19,83.97 89.19,71.94 88.24,70.99 88.24,54.35 88.97,53.62 v1(91.84,53.62) ; U7.5 v1(92.75,25.6)
  03_SIG1 w0.133: v1(92.75,25.6) 93.38,26.23 93.38,28.38 94.89,29.89 94.89,48.27 94.73,48.43 94.19,48.43 94.03,48.27 94.03,44.59 93.87,44.43 93.46,44.43 93.29,44.6 93.29,52.86 93.04,53.11 92.66,53.11 92.28,52.73 92.28,45.02 91.92,44.66 91.32,44.66 91.03,44.95 91.03,52.81 v1(91.84,53.62)
  BOTTOM w0.191: J500.A30 v1(91.1,85.87)
DAD_SEL_1: length 95.7
  TOP w0.191: v1(95.58,25.38) 95.3,25.1 U7.4 ; v1(96.18,85.87) 95.54,85.24 95.54,84.17 95.35,83.97 93.21,83.97 90.46,81.22 90.46,71.81 88.96,70.3 88.96,55.37 89.57,54.76 93.63,54.76 94.18,54.21 94.18,53.36 93.73,52.91 90.36,52.91 89.96,52.51 89.96,51.1 90.44,50.62 99.27,50.62 100.19,49.71 100.19,43.76 99.97,43.54 99.44,43.54 99.18,43.8 99.18,47.19 98.93,47.44 98.35,47.44 98.1,47.19 v1(98.1,44.3)
  03_SIG1 w0.133: v1(98.1,44.3) 98.71,43.69 98.71,28.51 v1(95.58,25.38)
  BOTTOM w0.191: J500.A34 v1(96.18,85.87)
DAD_STRB: length 96.4
  TOP w0.191: v1(101.26,85.87) 100.62,85.24 100.62,73.64 97.91,70.92 92.47,70.92 91.42,69.87 91.42,56.87 92.41,55.89 99.98,55.89 100.82,55.05 100.82,53.33 100.27,52.78 95.53,52.78 94.92,52.18 90.9,52.18 90.66,51.93 90.66,51.44 90.85,51.25 100.49,51.25 101.25,50.49 101.25,41.21 98.66,38.62 96.78,38.62 96.03,37.87 96.03,35.33 96.45,34.91 96.45,31.55 95.5,30.6 U7.15
  BOTTOM w0.191: J500.A38 v1(101.26,85.87)
DMD_RSTZ: length 140.3
  TOP w0.191: U7.59 76.97,24.1 74.76,26.32 74.76,47.43 73.87,48.32 58.98,48.32 57.94,47.28 28.7,47.28 28.42,47.56 28.42,48.13 26.4,50.15 26.4,52.62 27.83,54.05 v1(30.08,54.05) 30.73,54.05 35.72,59.04 47.05,59.04 53.63,65.62 53.63,85.24 v1(54.27,85.87)
  BOTTOM w0.191: J500.A02 v1(54.27,85.87) ; U9.4 27.92,52.22 29.75,54.05 v1(30.08,54.05) 30.23,53.9 R26.2
DMD_RSTZ_1V8: length 26.7
  TOP w0.191: U8.G4 v1(20.8,36.04)
  03_SIG1 w0.133: v1(20.8,36.04) 20.12,36.73 16.68,36.73 16.15,37.26 16.15,41.23 14.52,42.86 14.52,51.12 16.91,53.51 v1(18.45,53.51)
  BOTTOM w0.191: R22.1 18.71,53.25 v1(18.45,53.51)
DMD_TEMP_N: length 68
  TOP w0.107: v1(40.74,12.42) 41.29,12.42 41.45,12.26 41.45,11.69 42.15,10.99 68.75,10.99 70.48,9.26 92.16,9.26 C78.1 92.95,9.24 93.69,9.24 94.2,8.74 R35.1
  TOP w0.191: U8.W16 v1(37.31,19.53)
  08_SIG3 w0.108: v1(37.31,19.53) 37.72,19.53 37.82,19.42 37.82,13.83 38.33,13.32 41.2,13.32 41.41,13.12 41.41,12.56 41.27,12.42 v1(40.74,12.42)
DMD_TEMP_P: length 68
  TOP w0.107: v1(42.27,12.42) 41.9,12.42 41.69,12.21 41.69,11.78 42.25,11.22 44,11.22 44.14,11.37 44.14,11.54 44.28,11.68 44.49,11.68 44.63,11.54 44.63,11.37 44.77,11.22 68.84,11.22 70.58,9.49 92.16,9.49 C78.2 92.98,9.47 93.66,9.47 94.19,10.01 R34.1
  TOP w0.191: U8.W17 v1(38.58,19.53)
  08_SIG3 w0.108: v1(38.58,19.53) 38.18,19.53 38.08,19.42 38.08,13.94 38.44,13.58 41.31,13.58 41.66,13.22 41.66,12.57 41.81,12.42 v1(42.27,12.42)
I2C_SCL_3P3V: length 9.9
  TOP w0.191: R32.2 105.45,10.35 U11.8 102.97,10.36 101.22,10.36 100.21,9.35 J3.1
I2C_SDA_3P3V: length 8.4
  TOP w0.191: J3.2 101.46,9.41 101.75,9.7 102.98,9.7 U11.7 105.42,9.7 R33.2
M_DCLKA_N: length 124.4
  TOP w0.108: U8.H23 v1(46.2,34.77)
  03_SIG1 w0.108: v1(46.2,34.77) 46.05,34.77 45.91,34.91 45.91,35.21 46.05,35.35 46.54,35.35 46.71,35.18 46.71,34.48 46.49,34.26 45.79,34.26 45.39,34.66 45.39,36.09 43.16,38.32 43.16,45.65 44.49,46.98 46.58,46.98 51.95,52.34 51.95,58.18 58.46,64.69 58.46,68.25 58.85,68.64 63.74,68.64 64.37,68.01 64.37,60.55 64.71,60.21 65.27,60.21 65.62,60.56 65.62,68.23 66.03,68.64 71.67,68.64 72.22,68.09 72.22,61.13 72.7,60.65 73.38,60.65 73.81,61.08 73.81,68.16 74.29,68.64 78.33,68.64 78.7,69.01 78.7,69.43 78.33,69.8 58,69.8 57.67,70.14 57.67,72.68 57.5,72.84 57.5,73.1 57.67,73.27 57.99,73.27 v1(58.08,73.17)
  BOTTOM w0.108: J500.K05 v1(58.08,73.17)
M_DCLKA_P: length 124.4
  TOP w0.108: U8.G23 v1(46.2,36.04)
  03_SIG1 w0.108: v1(56.81,73.17) 57.41,72.57 57.41,70.03 57.9,69.55 78.23,69.55 78.45,69.32 78.45,69.12 78.23,68.89 74.19,68.89 73.55,68.26 73.55,61.19 73.27,60.9 72.8,60.9 72.48,61.23 72.48,68.19 71.77,68.89 65.93,68.89 65.37,68.33 65.37,60.67 65.17,60.47 64.82,60.47 64.63,60.66 64.63,68.12 63.85,68.89 58.74,68.89 58.2,68.36 58.2,64.79 51.69,58.28 51.69,52.45 46.48,47.23 44.39,47.23 42.91,45.75 42.91,38.21 45.14,35.98 45.14,34.56 45.69,34.01 46.6,34.01 46.97,34.38 46.97,35.28 v1(46.2,36.04)
  BOTTOM w0.108: J500.K04 v1(56.81,73.17)
M_DCLKB_N: length 124.5
  TOP w0.108: U8.T23 v1(46.2,23.34)
  08_SIG3 w0.108: v1(55.54,74.44) 55.14,74.44 55.03,74.33 55.03,72.93 57.07,70.89 59.56,70.89 62.51,67.95 81.17,67.95 81.57,67.54 81.57,66.97 81.16,66.57 66.21,66.57 65.56,65.93 65.56,57.28 65.15,56.87 64.55,56.87 64.16,57.26 64.16,66.21 63.99,66.38 63.7,66.38 63.53,66.21 63.53,56.71 55.78,48.97 54.88,48.97 54.23,48.32 54.23,47.46 51.16,44.4 51.16,30.13 50.28,29.25 46.21,29.25 45.61,28.65 45.61,23.03 45.88,22.76 46.12,22.76 46.28,22.92 46.28,23.27 v1(46.2,23.34)
  BOTTOM w0.108: J500.J03 v1(55.54,74.44)
M_DCLKB_P: length 124.5
  TOP w0.108: U8.U23 v1(46.2,22.07)
  08_SIG3 w0.108: v1(54.27,74.44) 54.67,74.44 54.78,74.33 54.78,72.83 56.97,70.64 59.46,70.64 62.4,67.69 81.06,67.69 81.32,67.44 81.32,67.08 81.06,66.82 66.1,66.82 65.31,66.03 65.31,57.39 65.04,57.12 64.66,57.12 64.42,57.36 64.42,66.31 64.09,66.64 63.59,66.64 63.27,66.31 63.27,56.82 55.68,49.23 54.78,49.23 53.97,48.42 53.97,47.57 50.91,44.5 50.91,30.24 50.18,29.51 46.1,29.51 45.35,28.76 45.35,22.92 v1(46.2,22.07)
  BOTTOM w0.108: J500.J02 v1(54.27,74.44)
M_DDA00_N: length 124.5
  TOP w0.108: U8.B18 v1(39.85,42.39)
  05_SIG2 w0.108: v1(79.67,82.06) 78.77,82.96 77.78,82.96 77.33,82.51 77.33,81.46 77.78,81.01 77.78,70.77 77.39,70.38 77.39,68.04 75.08,65.73 72.67,65.73 68.22,61.29 68.22,60.78 68.57,60.43 69.11,60.43 73.02,64.34 75.38,64.34 77.22,66.18 77.57,66.18 77.73,66.02 77.73,65.5 75.94,63.71 73.31,63.71 65.97,56.37 64.61,56.37 62.19,58.79 59.76,58.79 53.92,52.96 53.77,52.96 53.49,53.24 53.49,53.4 58.18,58.09 58.18,58.73 57.91,58.99 57.18,58.99 52.03,53.85 52.03,52.43 49.87,50.27 46.32,50.27 45.9,49.86 45.9,49.27 46.38,48.79 51.91,48.79 52.4,48.3 52.4,47.84 51.85,47.29 43.21,47.29 40.36,44.45 40.36,42.5 40.26,42.39 v1(39.85,42.39)
  BOTTOM w0.108: J500.D21 v1(79.67,82.06)
M_DDA00_P: length 124.5
  TOP w0.108: U8.B19 v1(41.12,42.39)
  05_SIG2 w0.108: v1(78.4,82.06) 78.4,81.99 78.6,81.79 78.9,81.79 79.05,81.94 79.05,82.32 78.66,82.71 77.89,82.71 77.58,82.4 77.58,81.57 78.03,81.11 78.03,70.66 77.65,70.28 77.65,67.93 75.19,65.48 72.77,65.48 68.48,61.18 68.48,60.89 68.68,60.69 69.01,60.69 72.91,64.59 75.27,64.59 77.11,66.43 77.67,66.43 77.98,66.13 77.98,65.39 76.04,63.45 73.41,63.45 66.07,56.11 64.51,56.11 62.08,58.54 59.87,58.54 54.03,52.7 53.67,52.7 53.23,53.14 53.23,53.5 57.92,58.19 57.92,58.62 57.8,58.74 57.29,58.74 52.29,53.74 52.29,52.33 49.98,50.02 46.42,50.02 46.16,49.75 46.16,49.38 46.49,49.05 52.01,49.05 52.65,48.41 52.65,47.74 51.96,47.04 43.31,47.04 40.62,44.34 40.62,42.5 40.72,42.39 v1(41.12,42.39)
  BOTTOM w0.108: J500.D20 v1(78.4,82.06)
M_DDA01_N: length 124.5
  TOP w0.108: U8.H24 v1(47.47,34.77)
  05_SIG2 w0.108: v1(82.21,83.33) 81.81,83.33 81.7,83.44 81.7,83.7 81.33,84.07 80.43,84.07 80.17,83.82 80.17,80.34 81.11,79.4 88.15,79.4 89.07,78.48 89.07,72.8 82.84,66.57 82.84,65.41 66.94,49.5 63.08,49.5 58.22,44.64 58.22,37.41 62.83,32.8 65.3,32.8 66.6,31.51 66.6,28.89 65.23,27.52 55.92,27.52 53.6,29.84 53.6,39 51.98,40.62 47.13,40.62 46.72,40.2 46.72,35.46 46.92,35.26 47.37,35.26 47.47,35.15 v1(47.47,34.77)
  BOTTOM w0.108: J500.C23 v1(82.21,83.33)
M_DDA01_P: length 124.5
  TOP w0.108: U8.G24 v1(47.47,36.04)
  05_SIG2 w0.108: v1(47.47,36.04) 47.62,36.04 47.73,35.93 47.73,35.62 47.62,35.51 47.1,35.51 46.97,35.64 46.97,40.1 47.23,40.36 51.88,40.36 53.35,38.9 53.35,29.73 55.81,27.27 65.34,27.27 66.85,28.79 66.85,31.61 65.41,33.06 62.93,33.06 58.47,37.52 58.47,44.53 63.19,49.25 67.05,49.25 83.1,65.3 83.1,66.47 89.32,72.69 89.32,78.59 88.25,79.66 81.22,79.66 80.43,80.44 80.43,83.71 80.54,83.82 81.22,83.82 81.45,83.59 81.45,83.02 81.32,82.89 81.05,82.89 80.94,83 v1(80.94,83.33)
  BOTTOM w0.108: J500.C22 v1(80.94,83.33)
M_DDA02_N: length 124.5
  TOP w0.108: U8.L23 v1(46.2,30.96)
  03_SIG1 w0.108: v1(46.2,30.96) 46.2,31.36 46.31,31.47 46.65,31.47 46.96,31.78 46.96,32.57 47.13,32.74 47.85,32.74 48.24,33.13 48.24,36.44 47.88,36.8 45.9,36.8 44.43,38.28 44.43,44.83 45.51,45.91 48.44,45.91 49.65,47.12 49.65,48.5 52.89,51.73 52.89,57.8 56.08,60.99 57.47,60.99 58.3,61.82 58.3,63.22 59.38,64.3 59.38,67.41 59.72,67.75 63.04,67.75 63.44,67.35 63.44,59.71 64.02,59.14 65.8,59.14 66.49,59.84 66.49,67.21 67.02,67.74 70.75,67.74 71.28,67.2 71.28,60.23 71.86,59.66 74.4,59.66 74.91,60.17 74.91,66.16 75.11,66.36 75.54,66.36 75.73,66.17 75.73,60.16 76.11,59.78 76.79,59.78 77.19,60.18 77.19,67.23 77.59,67.63 80.54,67.63 81.18,68.28 81.18,74.53 82.21,75.55 v1(82.21,75.71)
  BOTTOM w0.108: J500.H23 v1(82.21,75.71)
M_DDA02_P: length 124.5
  TOP w0.108: U8.K23 v1(46.2,32.23)
  03_SIG1 w0.108: v1(46.2,32.23) 46.2,31.83 46.31,31.72 46.55,31.72 46.71,31.88 46.71,32.68 47.02,32.99 47.74,32.99 47.99,33.24 47.99,36.34 47.77,36.55 45.8,36.55 44.17,38.18 44.17,44.94 45.4,46.16 48.33,46.16 49.4,47.23 49.4,48.6 52.63,51.84 52.63,57.91 55.98,61.25 57.37,61.25 58.05,61.93 58.05,63.33 59.12,64.41 59.12,67.51 59.62,68.01 63.14,68.01 63.7,67.45 63.7,59.82 64.12,59.4 65.69,59.4 66.24,59.94 66.24,67.31 66.92,67.99 70.85,67.99 71.54,67.31 71.54,60.34 71.96,59.91 74.3,59.91 74.66,60.27 74.66,66.27 75,66.62 75.64,66.62 75.98,66.28 75.98,60.27 76.22,60.03 76.69,60.03 76.93,60.28 76.93,67.33 77.49,67.89 80.43,67.89 80.93,68.39 80.93,74.63 81.58,75.28 81.58,75.6 81.47,75.71 v1(80.94,75.71)
  BOTTOM w0.108: J500.H22 v1(80.94,75.71)
M_DDA03_N: length 124.4
  TOP w0.108: U8.C18 v1(39.85,41.12)
  05_SIG2 w0.108: v1(80.94,76.98) 80.54,76.98 80.43,76.87 80.43,65.31 66.35,51.24 62.27,51.24 59.13,48.1 58.45,48.1 58.14,48.41 58.14,49.06 60.63,51.55 60.63,51.85 60.4,52.08 60.05,52.08 56.64,48.67 56.64,32.01 57.54,31.12 64.54,31.12 65.01,30.65 65.01,29.65 64.48,29.13 56.78,29.13 55.23,30.68 55.23,44.31 54.27,45.26 44.4,45.26 43.16,44.02 43.16,40.77 42.75,40.36 40.76,40.36 40.36,40.76 40.36,41.01 40.25,41.12 v1(39.85,41.12)
  BOTTOM w0.108: J500.G22 v1(80.94,76.98)
M_DDA03_P: length 124.4
  TOP w0.108: U8.C19 v1(41.12,41.12)
  05_SIG2 w0.108: v1(41.12,41.12) 41.12,41.47 41.01,41.58 40.72,41.58 40.62,41.47 40.62,40.86 40.86,40.61 42.64,40.61 42.91,40.88 42.91,44.12 44.3,45.51 54.38,45.51 55.48,44.41 55.48,30.79 56.89,29.38 64.38,29.38 64.75,29.76 64.75,30.55 64.44,30.86 57.43,30.86 56.39,31.91 56.39,48.78 59.94,52.33 60.51,52.33 60.89,51.95 60.89,51.45 58.4,48.96 58.4,48.51 58.55,48.36 59.03,48.36 62.16,51.49 66.25,51.49 80.18,65.42 80.18,76.87 80.07,76.98 v1(79.67,76.98)
  BOTTOM w0.108: J500.G21 v1(79.67,76.98)
M_DDA04_N: length 124.4
  TOP w0.108: U8.A19 v1(41.12,43.66)
  05_SIG2 w0.108: v1(86.02,75.71) 85.62,75.71 85.51,75.82 85.51,77.36 85.13,77.74 79.26,77.74 78.62,77.1 78.62,65.13 76.28,62.8 73.67,62.8 64.94,54.07 64.94,53.54 65.2,53.28 65.76,53.28 73.84,61.36 74.25,61.36 74.36,61.25 74.36,60.92 65.85,52.42 65.14,52.42 63.63,53.92 63.63,56.11 61.86,57.88 60.29,57.88 52.49,50.08 52.49,49.59 52.86,49.23 53.34,49.23 59.97,55.86 60.33,55.86 60.67,55.52 60.67,55.23 53.99,48.55 53.99,47.73 52.66,46.4 43.81,46.4 41.63,44.21 41.63,43.77 41.52,43.66 v1(41.12,43.66)
  BOTTOM w0.108: J500.H26 v1(86.02,75.71)
M_DDA04_P: length 124.4
  TOP w0.108: U8.A20 v1(42.39,43.66)
  05_SIG2 w0.108: v1(42.39,43.66) 42.39,43.3 42.29,43.2 42.04,43.2 41.89,43.35 41.89,44.11 43.92,46.14 52.76,46.14 54.25,47.62 54.25,48.45 60.92,55.13 60.92,55.63 60.44,56.11 59.87,56.11 53.24,49.48 52.96,49.48 52.75,49.7 52.75,49.97 60.4,57.62 61.75,57.62 63.37,56 63.37,53.82 65.03,52.16 65.96,52.16 74.61,60.82 74.61,61.36 74.36,61.62 73.73,61.62 65.65,53.54 65.3,53.54 65.2,53.64 65.2,53.96 73.77,62.54 76.38,62.54 78.87,65.03 78.87,76.99 79.36,77.49 85.03,77.49 85.26,77.26 85.26,75.82 85.15,75.71 v1(84.75,75.71)
  BOTTOM w0.108: J500.H25 v1(84.75,75.71)
M_DDA05_N: length 124.5
  TOP w0.108: U8.E24 v1(47.47,38.58)
  03_SIG1 w0.108: v1(84.75,76.98) 84.39,76.62 84.39,76.3 84.24,76.15 84.24,67.61 83.89,67.26 83.31,67.26 82.97,67.6 82.97,69.5 82.73,69.73 82.37,69.73 82.12,69.49 82.12,67.34 81.5,66.72 78.66,66.72 78.19,66.26 78.19,59.74 77.13,58.67 71.21,58.67 70.37,59.52 70.37,66.56 70.06,66.87 69.64,66.87 69.39,66.62 69.39,59.34 69.05,59.01 68.52,59.01 68.19,59.34 68.19,66.65 67.99,66.85 67.71,66.85 67.48,66.63 67.48,59.32 66.4,58.23 63.62,58.23 62.37,59.49 62.37,60.23 60.98,61.62 60.98,62.81 61.48,63.31 61.48,66.5 61.11,66.86 60.61,66.86 60.3,66.55 60.3,63.61 59.25,62.57 59.25,61.1 58.16,60 56.4,60 53.89,57.49 53.89,49.81 48.85,44.78 46.56,44.78 45.7,43.92 45.7,40.86 45.94,40.61 47.86,40.61 48.24,40.23 48.24,39.39 47.94,39.09 47.58,39.09 47.47,38.98 v1(47.47,38.58)
  BOTTOM w0.108: J500.G25 v1(84.75,76.98)
M_DDA05_P: length 124.5
  TOP w0.108: U8.D24 v1(47.47,39.85)
  03_SIG1 w0.108: v1(83.48,76.98) 83.98,76.98 84.14,76.83 84.14,76.4 83.99,76.25 83.99,67.72 83.79,67.52 83.41,67.52 83.22,67.7 83.22,69.6 82.84,69.99 82.26,69.99 81.87,69.6 81.87,67.45 81.4,66.98 78.55,66.98 77.94,66.36 77.94,59.84 77.02,58.93 71.31,58.93 70.62,59.62 70.62,66.67 70.17,67.12 69.53,67.12 69.13,66.72 69.13,59.45 68.95,59.26 68.62,59.26 68.44,59.44 68.44,66.75 68.09,67.1 67.6,67.1 67.23,66.73 67.23,59.42 66.29,58.49 63.73,58.49 62.62,59.59 62.62,60.33 61.23,61.72 61.23,62.7 61.73,63.2 61.73,66.6 61.22,67.11 60.5,67.11 60.05,66.66 60.05,63.72 59,62.67 59,61.21 58.05,60.26 56.29,60.26 53.63,57.6 53.63,49.92 48.74,45.03 46.45,45.03 45.44,44.02 45.44,40.75 45.84,40.36 47.75,40.36 47.99,40.12 47.99,39.5 47.83,39.34 47.58,39.34 47.47,39.45 v1(47.47,39.85)
  BOTTOM w0.108: J500.G24 v1(83.48,76.98)
M_DDA06_N: length 124.5
  TOP w0.108: U8.K25 v1(48.74,32.23)
  05_SIG2 w0.108: v1(83.48,82.06) 83.08,82.06 82.97,82.17 82.97,82.32 83.21,82.56 83.69,82.56 83.99,82.26 83.99,80.45 84.45,79.99 88.86,79.99 90.34,78.51 90.34,71.37 67.19,48.22 63.37,48.22 59.12,43.97 59.12,37.82 62.97,33.97 67.25,33.97 68.53,32.68 68.53,27.85 67.22,26.54 55.24,26.54 52.78,29.01 52.78,38.29 51.72,39.34 48.42,39.34 47.98,38.91 47.98,33.14 48.38,32.74 48.88,32.74 48.99,32.63 48.99,32.34 48.88,32.23 v1(48.74,32.23)
  BOTTOM w0.108: J500.D24 v1(83.48,82.06)
M_DDA06_P: length 124.5
  TOP w0.108: U8.J25 v1(48.74,33.5)
  05_SIG2 w0.108: v1(82.21,82.06) 82.61,82.06 82.72,82.17 82.72,82.43 83.1,82.81 83.79,82.81 84.24,82.36 84.24,80.55 84.55,80.24 88.96,80.24 90.59,78.62 90.59,71.26 67.29,47.97 63.47,47.97 59.37,43.87 59.37,37.92 63.07,34.22 67.35,34.22 68.79,32.79 68.79,27.74 67.33,26.29 55.14,26.29 52.52,28.91 52.52,38.18 51.62,39.09 48.52,39.09 48.24,38.8 48.24,33.24 48.48,32.99 48.64,32.99 48.74,33.1 v1(48.74,33.5)
  BOTTOM w0.108: J500.D23 v1(82.21,82.06)
M_DDA07_N: length 124.5
  TOP w0.108: U8.C26 v1(50.01,41.12)
  03_SIG1 w0.108: v1(89.83,75.71) 89.07,76.48 88.2,76.48 87.8,76.08 87.8,65.8 85.09,63.09 81.42,63.09 80.86,62.53 80.86,61.21 81.22,60.85 89.96,60.85 90.14,60.67 90.14,60.28 89.98,60.11 81.52,60.11 80.86,59.46 80.86,55.2 77.33,51.67 57.82,51.67 57.22,51.07 57.22,49.24 57.98,48.48 75.78,48.48 76.1,48.16 76.1,47.51 75.76,47.17 57.62,47.17 51.06,40.61 50.12,40.61 50.01,40.72 v1(50.01,41.12)
  BOTTOM w0.108: J500.H29 v1(89.83,75.71)
M_DDA07_P: length 124.5
  TOP w0.108: U8.D26 v1(50.01,39.85)
  03_SIG1 w0.108: v1(88.56,75.71) 88.63,75.64 89.02,75.64 89.13,75.75 89.13,76.05 88.96,76.22 88.3,76.22 88.05,75.98 88.05,65.69 85.2,62.84 81.52,62.84 81.11,62.43 81.11,61.32 81.33,61.1 90.07,61.1 90.39,60.77 90.39,60.17 90.08,59.86 81.62,59.86 81.11,59.35 81.11,55.1 77.44,51.42 57.93,51.42 57.47,50.97 57.47,49.34 58.08,48.73 75.88,48.73 76.35,48.27 76.35,47.4 75.86,46.91 57.72,46.91 51.17,40.36 50.12,40.36 50.01,40.25 v1(50.01,39.85)
  BOTTOM w0.108: J500.H28 v1(88.56,75.71)
M_DDA08_N: length 124.5
  TOP w0.108: U8.C21 v1(43.66,41.12)
  05_SIG2 w0.108: v1(88.56,76.98) 88.05,76.47 88.05,72.74 87.19,71.87 85.59,71.87 85.25,72.21 85.25,74.76 85.07,74.95 84.24,74.95 83.99,75.21 83.99,76.11 83.88,76.22 81.88,76.22 81.7,76.04 81.7,72.26 82.05,71.92 83.07,71.92 83.46,71.53 83.46,69.9 83,69.44 81.94,69.44 81.73,69.23 81.73,65.29 66.67,50.24 62.63,50.24 57.58,45.19 57.58,33.08 58.49,32.17 65.04,32.17 65.95,31.26 65.95,29.13 65.04,28.22 56.17,28.22 54.3,30.1 54.3,40.64 50.57,44.37 44.78,44.37 44.43,44.01 44.43,41.89 44.17,41.63 43.77,41.63 43.66,41.52 v1(43.66,41.12)
  BOTTOM w0.108: J500.G28 v1(88.56,76.98)
M_DDA08_P: length 124.4
  TOP w0.108: U8.B21 v1(43.66,42.39)
  05_SIG2 w0.108: v1(87.29,76.98) 87.42,77.11 87.68,77.11 87.8,77 87.8,72.84 87.09,72.13 85.7,72.13 85.51,72.31 85.51,74.87 85.17,75.2 84.35,75.2 84.24,75.31 84.24,76.22 83.98,76.47 81.77,76.47 81.44,76.14 81.44,72.16 81.94,71.66 82.97,71.66 83.21,71.42 83.21,70.01 82.89,69.69 81.83,69.69 81.48,69.34 81.48,65.4 66.57,50.49 62.52,50.49 57.33,45.3 57.33,32.98 58.39,31.92 64.93,31.92 65.69,31.16 65.69,29.24 64.93,28.48 56.28,28.48 54.55,30.2 54.55,40.74 50.67,44.62 44.67,44.62 44.17,44.12 44.17,41.99 44.07,41.88 43.77,41.88 43.66,41.99 v1(43.66,42.39)
  BOTTOM w0.108: J500.G27 v1(87.29,76.98)
M_DDA09_N: length 124.4
  TOP w0.108: U8.G25 v1(48.74,36.04)
  05_SIG2 w0.108: v1(48.74,36.04) 48.74,36.44 48.85,36.55 49.23,36.55 49.51,36.83 49.51,37.55 49.78,37.82 50.72,37.82 51.63,36.91 51.63,28.42 54.7,25.35 71.07,25.35 72.68,26.95 72.68,33.55 70.99,35.24 63.44,35.24 60.26,38.41 60.26,43.44 63.73,46.91 68.86,46.91 87.19,65.24 88.48,65.24 91.86,68.62 91.86,81.3 91.61,81.55 87.03,81.55 86.91,81.67 86.91,81.82 87.16,82.06 v1(87.29,82.06)
  BOTTOM w0.108: J500.D27 v1(87.29,82.06)
M_DDA09_P: length 124.4
  TOP w0.108: U8.F25 v1(48.74,37.31)
  05_SIG2 w0.108: v1(48.74,37.31) 48.75,37.31 48.75,36.91 48.85,36.8 49.12,36.8 49.25,36.94 49.25,37.65 49.68,38.08 50.83,38.08 51.89,37.02 51.89,28.52 54.81,25.6 70.97,25.6 72.42,27.06 72.42,33.44 70.88,34.98 63.33,34.98 60.01,38.31 60.01,43.55 63.63,47.17 68.76,47.17 87.08,65.49 88.37,65.49 91.61,68.73 91.61,81.19 91.5,81.3 86.93,81.3 86.66,81.56 86.66,81.94 86.43,82.17 86.13,82.17 v1(86.02,82.06)
  BOTTOM w0.108: J500.D26 v1(86.02,82.06)
M_DDA10_N: length 124.5
  TOP w0.108: U8.A24 v1(47.47,43.66)
  03_SIG1 w0.108: v1(47.47,43.66) 47.47,43.26 47.58,43.15 49.28,43.15 54.09,47.97 54.09,49 54.98,49.89 54.98,57.5 56.84,59.36 61.13,59.36 62.97,57.52 75.76,57.52 76.07,57.21 76.07,56.64 75.68,56.25 62.47,56.25 60.52,58.19 57.43,58.19 56.36,57.12 56.36,56.83 56.6,56.59 56.96,56.59 57.79,57.42 60.35,57.42 62.3,55.46 77.29,55.46 79.04,57.22 79.04,64.91 79.57,65.44 84.27,65.44 85.26,66.42 85.26,83.76 85.58,84.08 86.54,84.08 v1(87.29,83.33)
  BOTTOM w0.108: J500.C27 v1(87.29,83.33)
M_DDA10_P: length 124.5
  TOP w0.108: U8.B24 v1(47.47,42.39)
  03_SIG1 w0.108: v1(86.02,83.33) 86.09,83.27 86.48,83.27 86.59,83.37 86.59,83.67 86.43,83.83 85.69,83.83 85.51,83.65 85.51,66.32 84.38,65.18 79.67,65.18 79.29,64.8 79.29,57.11 77.39,55.21 62.2,55.21 60.24,57.17 57.9,57.17 57.06,56.33 56.5,56.33 56.1,56.73 56.1,57.22 57.33,58.45 60.63,58.45 62.57,56.5 75.57,56.5 75.81,56.74 75.81,57.1 75.65,57.26 62.87,57.26 61.03,59.11 56.95,59.11 55.24,57.39 55.24,49.78 54.35,48.89 54.35,47.86 49.39,42.9 47.58,42.9 47.47,42.79 v1(47.47,42.39)
  BOTTOM w0.108: J500.C26 v1(86.02,83.33)
M_DDA11_N: length 124.5
  TOP w0.108: U8.J26 v1(50.01,33.5)
  03_SIG1 w0.108: v1(50.01,33.5) 49.9,33.38 49.9,33.07 50.06,32.9 54.49,32.9 55.25,33.66 55.25,40.69 56.1,41.55 60.03,41.55 60.82,40.76 60.82,37.08 61.51,36.38 69.58,36.38 80.29,47.09 80.29,50.48 87.7,57.9 109.41,57.9 109.78,58.27 109.78,58.73 109.32,59.2 98.48,59.2 94.98,62.7 92.3,62.7 89.57,65.43 89.57,68.18 92.59,71.2 93.78,71.2 94.15,71.57 94.15,76.1 94.04,76.21 93.22,76.21 92.98,75.97 92.98,75.61 93.12,75.47 93.4,75.47 v1(93.64,75.71)
  BOTTOM w0.108: J500.H32 v1(93.64,75.71)
M_DDA11_P: length 124.5
  TOP w0.108: U8.K26 v1(50.01,32.23)
  03_SIG1 w0.108: v1(92.37,75.71) 93.12,76.46 94.14,76.46 94.4,76.2 94.4,71.46 93.88,70.94 92.69,70.94 89.83,68.07 89.83,65.54 92.41,62.95 95.08,62.95 98.58,59.45 109.42,59.45 110.04,58.84 110.04,58.16 109.52,57.64 87.81,57.64 80.54,50.38 80.54,46.98 69.69,36.13 61.41,36.13 60.56,36.97 60.56,40.66 59.93,41.29 56.2,41.29 55.5,40.59 55.5,33.55 54.6,32.65 50.43,32.65 v1(50.01,32.23)
  BOTTOM w0.108: J500.H31 v1(92.37,75.71)
M_DDA12_N: length 124.5
  TOP w0.108: U8.D25 v1(48.74,39.85)
  03_SIG1 w0.108: v1(48.74,39.85) 48.74,40.25 48.85,40.36 49.1,40.36 49.25,40.21 49.25,39.38 49.54,39.09 51.51,39.09 58.18,45.76 76.18,45.76 77.41,46.99 77.41,48.58 76.37,49.62 58.73,49.62 58.45,49.9 58.45,50.25 58.69,50.49 78.19,50.49 82.11,54.4 82.11,58.32 82.37,58.57 93.01,58.57 93.73,59.3 93.73,61.27 93.01,61.99 87.47,61.99 86.9,62.56 86.9,63.16 88.94,65.2 88.94,70.53 90.18,71.77 90.96,71.77 91.86,72.67 91.86,76.24 92.01,76.39 92.01,76.62 v1(92.37,76.98)
  BOTTOM w0.108: J500.G31 v1(92.37,76.98)
M_DDA12_P: length 124.5
  TOP w0.108: U8.C25 v1(48.74,41.12)
  03_SIG1 w0.108: v1(91.1,76.98) 91.6,76.98 91.76,76.83 91.76,76.49 91.61,76.35 91.61,72.78 90.86,72.02 90.07,72.02 88.69,70.64 88.69,65.31 86.64,63.26 86.64,62.45 87.36,61.73 92.91,61.73 93.48,61.16 93.48,59.4 92.9,58.83 82.26,58.83 81.86,58.42 81.86,54.51 78.09,50.74 58.58,50.74 58.2,50.36 58.2,49.79 58.63,49.36 76.26,49.36 77.16,48.47 77.16,47.09 76.08,46.01 58.08,46.01 51.41,39.34 49.64,39.34 49.5,39.48 49.5,40.32 49.21,40.61 48.85,40.61 48.74,40.72 v1(48.74,41.12)
  BOTTOM w0.108: J500.G30 v1(91.1,76.98)
M_DDA13_N: length 124.5
  TOP w0.108: U8.E23 v1(46.2,38.58)
  03_SIG1 w0.108: v1(46.2,38.58) 46.2,38.98 46.31,39.09 46.47,39.09 46.7,38.86 46.7,38.08 46.96,37.82 48.98,37.82 49.25,37.55 49.25,31.83 49.61,31.47 55.15,31.47 56.78,33.1 56.78,39.93 57.21,40.37 59.23,40.37 59.63,39.97 59.63,36.28 60.7,35.21 70.28,35.21 81.85,46.79 81.85,50.39 88.16,56.7 110,56.7 110.96,57.66 110.96,59.4 109.92,60.43 104.65,60.43 99.15,65.93 99.15,70.25 96.94,72.46 96.94,74.89 97.09,75.04 97.09,75.35 v1(97.45,75.71)
  BOTTOM w0.108: J500.H35 v1(97.45,75.71)
M_DDA13_P: length 124.5
  TOP w0.108: U8.D23 v1(46.2,39.85)
  03_SIG1 w0.108: v1(96.18,75.71) 96.69,75.71 96.84,75.57 96.84,75.14 96.69,74.99 96.69,72.35 98.89,70.14 98.89,65.83 104.54,60.18 109.82,60.18 110.7,59.29 110.7,57.76 109.89,56.95 88.05,56.95 81.6,50.49 81.6,46.89 70.17,35.47 60.8,35.47 59.89,36.38 59.89,40.07 59.34,40.62 57.11,40.62 56.52,40.04 56.52,33.21 55.04,31.72 49.71,31.72 49.51,31.93 49.51,37.65 49.08,38.07 47.06,38.07 46.95,38.18 46.95,38.96 46.57,39.34 46.31,39.34 46.2,39.45 v1(46.2,39.85)
  BOTTOM w0.108: J500.H34 v1(96.18,75.71)
